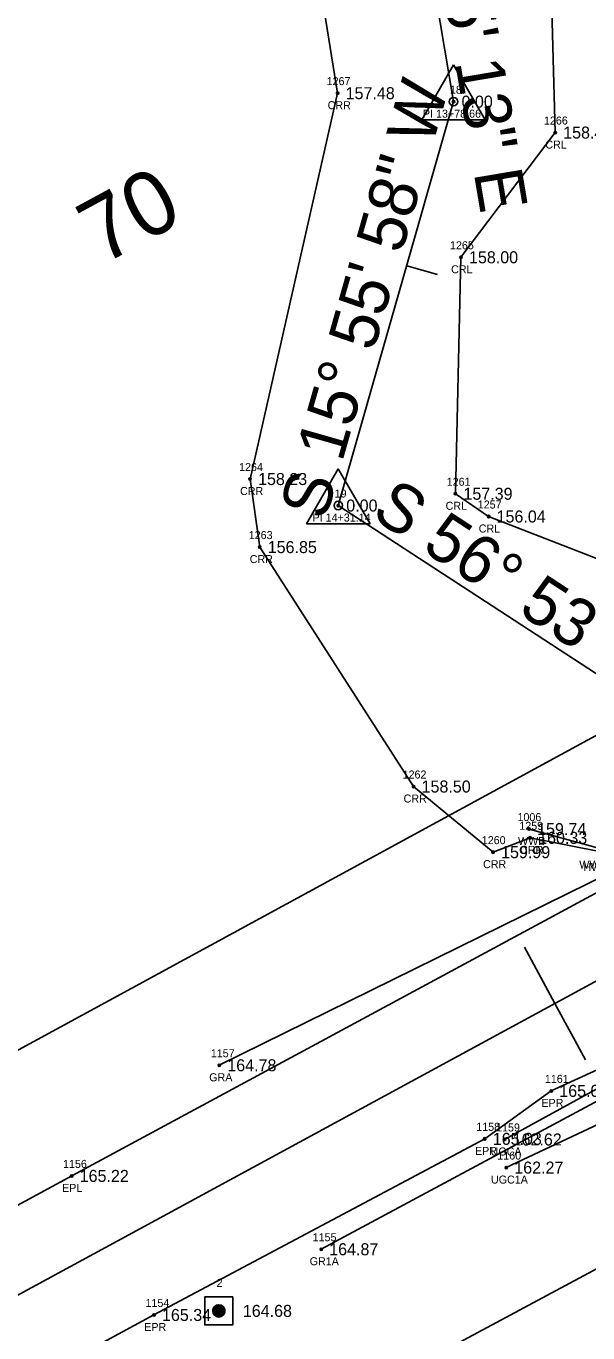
# Model space of a CAD drawing. Extents: x 2279339 to 2281902, y 1061267 to 1062892.
# Drawn here: x 2280137.2 to 2280207.4, y 1061741.1 to 1061904.3 of the extents above; entities that cross this region are included whole.
import ezdxf

# ---------------------------------------------------------------- set-up
doc = ezdxf.new("R2010")
doc.units = 0
for name, color, linetype in [('RD_EX_Bridge', 7, 'Continuous'), ('RD_EX_Bridge_txCode', 7, 'Continuous'), ('RD_EX_GuardRail', 7, 'Continuous'), ('RD_EX_GuardRail_txCode', 7, 'Continuous'), ('RD_EX_H2O', 7, 'Continuous'), ('RD_EX_H2O_txCode', 7, 'Continuous'), ('RD_EX_Road', 7, 'Continuous'), ('RD_EX_Road_txCode', 7, 'Continuous'), ('RD_EX_TX_Bridge_ELEV', 7, 'Continuous'), ('RD_EX_TX_GuardRail_ELEV', 7, 'Continuous'), ('RD_EX_TX_H2O_ELEV', 7, 'Continuous'), ('RD_EX_TX_Road_ELEV', 7, 'Continuous'), ('RD_EX_TX_UT_ELEV', 7, 'Continuous'), ('RD_EX_UT', 7, 'Continuous'), ('RD_EX_UT_txCode', 7, 'Continuous'), ('RD_EX_VEG', 7, 'Continuous'), ('RD_HC_Cl', 7, 'Continuous'), ('RD_HC_Data', 7, 'Continuous'), ('RD_HC_Data_Tic', 7, 'Continuous'), ('RD_HC_Survey', 7, 'Continuous'), ('RD_HC_Survey_ELEV', 7, 'Continuous'), ('RD_HC_Survey_txCode', 7, 'Continuous'), ('RD_HC_TX_Sta50', 7, 'Continuous'), ('RD_HC_txCode', 7, 'Continuous'), ('RD_SMD_Locator', 7, 'Continuous')]:
    doc.layers.add(name, color=color, linetype=linetype)

msp = doc.modelspace()

# ---------------------------------------------------------------- linework, layer by layer
at = {"layer": 'RD_EX_Bridge'}
msp.add_line((2280210.72, 1061801.1), (2280200.05, 1061804.04), dxfattribs=at)
at = {"layer": 'RD_EX_GuardRail'}
msp.add_line((2280174.08, 1061751.56), (2280309.28, 1061824.13), dxfattribs=at)
msp.add_lwpolyline([(2280161.35, 1061774.54), (2280212.91, 1061799.96), (2280228.59, 1061807.39), (2280248.74, 1061818.9), (2280296.23, 1061848.19)], dxfattribs=at)
at = {"layer": 'RD_EX_H2O'}
for points in [[(2280211.16, 1061800.79), (2280200.18, 1061802.95), (2280195.55, 1061801.16), (2280185.62, 1061809.36), (2280166.4, 1061839.27), (2280165.19, 1061847.77), (2280176.13, 1061895.97), (2280173.38, 1061913.11), (2280146.96, 1061940.88), (2280090.97, 1061964.76), (2280049.27, 1062002.4), (2280058.65, 1062048.88), (2280050.78, 1062064.28), (2280035.9, 1062083.09), (2280001.73, 1062095.49), (2279975.65, 1062129.45), (2279976.82, 1062173.44)], [(2280247.67, 1061820.22), (2280254.15, 1061833.04), (2280250.13, 1061833.61), (2280244.17, 1061836.72), (2280240.97, 1061826.97), (2280234.88, 1061827.59), (2280194.99, 1061843.09), (2280190.85, 1061845.93), (2280191.54, 1061875.47), (2280203.31, 1061891.05), (2280202.74, 1061912.57), (2280161.92, 1061962.77), (2280106.66, 1061987.64), (2280081.48, 1062000.69), (2280077.59, 1062019.21), (2280091.23, 1062055.4), (2280068.77, 1062094.03), (2280025.87, 1062122.57), (2280008.58, 1062126.75), (2280003.39, 1062153.96)]]:
    msp.add_lwpolyline(points, dxfattribs=at)
at = {"layer": 'RD_EX_Road'}
for points in [[(2279554.31, 1061441.46), (2279636.61, 1061486.51), (2279673.46, 1061506.76), (2279683.06, 1061512.21), (2279723.14, 1061533.54), (2279809.28, 1061580.29), (2279896.91, 1061627.91), (2279977.07, 1061671.02), (2280059.64, 1061715.57), (2280142.91, 1061760.72), (2280228.83, 1061807.06), (2280306.04, 1061849.18), (2280392.98, 1061896.71), (2280482.82, 1061945.75), (2280567.83, 1061991.78), (2280649.94, 1062036.55), (2280660.56, 1062042.19), (2280676.12, 1062050.66), (2280737.28, 1062083.64), (2280828.54, 1062132.77), (2280887.86, 1062164.61), (2280934.91, 1062190.9)], [(2279906, 1061609.76), (2279987.33, 1061653.65), (2280069.09, 1061697.76), (2280153.19, 1061743.35), (2280194.51, 1061765.35), (2280202.82, 1061771.34), (2280211.47, 1061775.32), (2280215.93, 1061780.7), (2280225.22, 1061785.77), (2280231.78, 1061787.38), (2280251.88, 1061797.82), (2280255.66, 1061801.36), (2280256.83, 1061804.75), (2280266.2, 1061806.83), (2280270.78, 1061807.29), (2280284.33, 1061814.31), (2280315.09, 1061831.32), (2280403.05, 1061879.04)]]:
    msp.add_lwpolyline(points, dxfattribs=at)
at = {"layer": 'RD_EX_UT'}
for points in [[(2280196.99, 1061765.27), (2280221.15, 1061778.49), (2280271.76, 1061806.05)], [(2280197.2, 1061761.76), (2280217.04, 1061771.11), (2280221.15, 1061778.49)]]:
    msp.add_lwpolyline(points, dxfattribs=at)
at = {"layer": 'RD_EX_VEG'}
for points in [[(2279558.89, 1061483.89), (2279567.79, 1061465.98), (2279895.37, 1061645.37), (2280383.77, 1061911.19), (2280927.05, 1062203.11)], [(2279742.03, 1061456.73), (2279738.34, 1061498.5), (2279914.03, 1061591.25), (2280293.74, 1061794.82), (2280950.97, 1062158.54)]]:
    msp.add_lwpolyline(points, dxfattribs=at)
at = {"layer": 'RD_HC_Cl'}
for p, q in [((2279559.77, 1061433.17), (2280939.55, 1062181.67)), ((2280187.29, 1061914.59), (2280190.61, 1061894.91)), ((2280190.61, 1061894.91), (2280176.21, 1061844.46)), ((2280176.21, 1061844.46), (2280228.65, 1061810.26))]:
    msp.add_line(p, q, dxfattribs=at)
at = {"layer": 'RD_HC_Data'}
for p, q in [((2280186.64, 1061892.62), (2280190.61, 1061899.5)), ((2280190.61, 1061899.5), (2280194.58, 1061892.62)), ((2280186.64, 1061892.62), (2280194.58, 1061892.62)), ((2280172.24, 1061842.16), (2280176.21, 1061849.04)), ((2280176.21, 1061849.04), (2280180.18, 1061842.16)), ((2280172.24, 1061842.16), (2280180.18, 1061842.16))]:
    msp.add_line(p, q, dxfattribs=at)
for centre in [(2280190.61, 1061894.91), (2280176.21, 1061844.46)]:
    msp.add_circle(centre, 0.529, dxfattribs=at)
at = {"layer": 'RD_HC_Data_Tic'}
for p, q in [((2280184.76, 1061874.39), (2280188.6, 1061873.3)), ((2280203.28, 1061782.26), (2280199.46, 1061789.29)), ((2280203.28, 1061782.26), (2280207.09, 1061775.22))]:
    msp.add_line(p, q, dxfattribs=at)
at = {"layer": 'RD_HC_Survey'}
for p, q in [((2280160.54, 1061743.69), (2280160.54, 1061744.04)), ((2280160.57, 1061743.6), (2280160.57, 1061744.13)), ((2280160.59, 1061743.54), (2280160.59, 1061744.19)), ((2280160.62, 1061743.49), (2280160.62, 1061744.24)), ((2280160.64, 1061743.45), (2280160.64, 1061744.28)), ((2280160.67, 1061743.41), (2280160.67, 1061744.31)), ((2280160.69, 1061743.38), (2280160.69, 1061744.35)), ((2280160.72, 1061743.35), (2280160.72, 1061744.38)), ((2280160.74, 1061743.33), (2280160.74, 1061744.4)), ((2280160.77, 1061743.3), (2280160.77, 1061744.43)), ((2280160.79, 1061743.28), (2280160.79, 1061744.45)), ((2280160.82, 1061743.26), (2280160.82, 1061744.47)), ((2280160.84, 1061743.24), (2280160.84, 1061744.49)), ((2280160.86, 1061743.22), (2280160.86, 1061744.5)), ((2280160.89, 1061743.21), (2280160.89, 1061744.52)), ((2280160.91, 1061743.19), (2280160.91, 1061744.54)), ((2280160.94, 1061743.18), (2280160.94, 1061744.55)), ((2280160.96, 1061743.17), (2280160.96, 1061744.56)), ((2280160.99, 1061743.16), (2280160.99, 1061744.57)), ((2280161.01, 1061743.15), (2280161.01, 1061744.58)), ((2280161.04, 1061743.14), (2280161.04, 1061744.59)), ((2280161.06, 1061743.13), (2280161.06, 1061744.6)), ((2280161.09, 1061743.12), (2280161.09, 1061744.61)), ((2280161.11, 1061743.12), (2280161.11, 1061744.61)), ((2280161.14, 1061743.11), (2280161.14, 1061744.62)), ((2280161.16, 1061743.11), (2280161.16, 1061744.62)), ((2280161.19, 1061743.1), (2280161.19, 1061744.63)), ((2280161.21, 1061743.1), (2280161.21, 1061744.63)), ((2280161.24, 1061743.1), (2280161.24, 1061744.63)), ((2280161.26, 1061743.1), (2280161.26, 1061744.63)), ((2280161.29, 1061743.09), (2280161.29, 1061744.63)), ((2280161.31, 1061743.1), (2280161.31, 1061744.63)), ((2280161.34, 1061743.1), (2280161.34, 1061744.63)), ((2280161.36, 1061743.1), (2280161.36, 1061744.63)), ((2280161.38, 1061743.1), (2280161.38, 1061744.63)), ((2280161.41, 1061743.1), (2280161.41, 1061744.62)), ((2280161.43, 1061743.11), (2280161.43, 1061744.62)), ((2280161.46, 1061743.11), (2280161.46, 1061744.62)), ((2280161.48, 1061743.12), (2280161.48, 1061744.61)), ((2280161.51, 1061743.13), (2280161.51, 1061744.6)), ((2280161.53, 1061743.13), (2280161.53, 1061744.59)), ((2280161.56, 1061743.14), (2280161.56, 1061744.59)), ((2280161.58, 1061743.15), (2280161.58, 1061744.58)), ((2280161.61, 1061743.16), (2280161.61, 1061744.57)), ((2280161.63, 1061743.17), (2280161.63, 1061744.55)), ((2280161.66, 1061743.19), (2280161.66, 1061744.54)), ((2280161.68, 1061743.2), (2280161.68, 1061744.53)), ((2280161.71, 1061743.22), (2280161.71, 1061744.51)), ((2280161.73, 1061743.23), (2280161.73, 1061744.5)), ((2280161.76, 1061743.25), (2280161.76, 1061744.48)), ((2280161.78, 1061743.27), (2280161.78, 1061744.46)), ((2280161.81, 1061743.29), (2280161.81, 1061744.44)), ((2280161.83, 1061743.31), (2280161.83, 1061744.41)), ((2280161.85, 1061743.34), (2280161.85, 1061744.39)), ((2280161.88, 1061743.37), (2280161.88, 1061744.36)), ((2280161.9, 1061743.4), (2280161.9, 1061744.33)), ((2280161.93, 1061743.43), (2280161.93, 1061744.3)), ((2280161.95, 1061743.47), (2280161.95, 1061744.26)), ((2280161.98, 1061743.52), (2280161.98, 1061744.21)), ((2280162, 1061743.57), (2280162, 1061744.16)), ((2280162.03, 1061743.64), (2280162.03, 1061744.09)), ((2280162.05, 1061743.75), (2280162.05, 1061743.98))]:
    msp.add_line(p, q, dxfattribs=at)
msp.add_lwpolyline([(2280163.04, 1061745.61), (2280159.54, 1061745.61), (2280159.54, 1061742.11), (2280163.04, 1061742.11)], close=True, dxfattribs=at)
msp.add_circle((2280161.29, 1061743.86), 0.769, dxfattribs=at)
at = {"layer": 'RD_SMD_Locator'}
for centre in [(2280176.13, 1061895.97), (2280190.61, 1061894.91), (2280203.31, 1061891.05), (2280191.54, 1061875.47), (2280165.19, 1061847.77), (2280190.85, 1061845.93), (2280176.21, 1061844.46), (2280194.99, 1061843.09), (2280166.4, 1061839.27), (2280185.62, 1061809.36), (2280200.05, 1061804.04), (2280200.18, 1061802.95), (2280195.55, 1061801.16), (2280161.35, 1061774.54), (2280202.82, 1061771.34), (2280194.51, 1061765.35), (2280196.99, 1061765.27), (2280197.2, 1061761.76), (2280142.91, 1061760.72), (2280174.08, 1061751.56), (2280161.29, 1061743.86), (2280153.19, 1061743.35)]:
    msp.add_circle(centre, 0.15, dxfattribs=at)

# ---------------------------------------------------------------- texts
at = {"layer": 'RD_EX_Bridge_txCode'}
for s, p in [('1006', (2280198.6, 1061805.04)), ('WWB', (2280198.67, 1061802.04)), ('WWA 16ROCK', (2280206.32, 1061799.1)), ('HWA 16ROCK', (2280206.85, 1061798.79))]:
    msp.add_text(s, height=1, dxfattribs=at).set_placement(p)
at = {"layer": 'RD_EX_GuardRail_txCode'}
for s, p in [('1157', (2280160.29, 1061775.54)), ('GRA', (2280160.09, 1061772.54)), ('1155', (2280173.01, 1061752.56)), ('GR1A', (2280172.64, 1061749.56))]:
    msp.add_text(s, height=1, dxfattribs=at).set_placement(p)
at = {"layer": 'RD_EX_H2O_txCode'}
for s, p in [('1267', (2280174.76, 1061896.97)), ('CRR', (2280174.88, 1061893.97)), ('1266', (2280201.91, 1061892.05)), ('CRL', (2280202.08, 1061889.05)), ('1265', (2280190.17, 1061876.47)), ('CRL', (2280190.31, 1061873.47)), ('1264', (2280163.82, 1061848.77)), ('CRR', (2280163.94, 1061845.77)), ('1261', (2280189.76, 1061846.93)), ('CRL', (2280189.62, 1061843.93)), ('1257', (2280193.64, 1061844.09)), ('CRL', (2280193.76, 1061841.09)), ('1263', (2280165.03, 1061840.27)), ('CRR', (2280165.15, 1061837.27)), ('1262', (2280184.25, 1061810.36)), ('CRR', (2280184.37, 1061807.36)), ('1259', (2280198.83, 1061803.95)), ('1260', (2280194.14, 1061802.16)), ('CRR', (2280198.93, 1061800.95)), ('CRR', (2280194.3, 1061799.16))]:
    msp.add_text(s, height=1, dxfattribs=at).set_placement(p)
at = {"layer": 'RD_EX_Road_txCode'}
for s, p in [('1161', (2280202.02, 1061772.34)), ('EPR', (2280201.59, 1061769.34)), ('1158', (2280193.45, 1061766.35)), ('EPR', (2280193.29, 1061763.35)), ('1156', (2280141.83, 1061761.72)), ('EPL', (2280141.71, 1061758.72)), ('1154', (2280152.13, 1061744.35)), ('EPR', (2280151.97, 1061741.35))]:
    msp.add_text(s, height=1, dxfattribs=at).set_placement(p)
at = {"layer": 'RD_EX_TX_Bridge_ELEV'}
msp.add_text('159.74', height=1.5, dxfattribs=at).set_placement((2280201.05, 1061803.29))
at = {"layer": 'RD_EX_TX_GuardRail_ELEV'}
for s, p in [('164.78', (2280162.35, 1061773.79)), ('164.87', (2280175.08, 1061750.81))]:
    msp.add_text(s, height=1.5, dxfattribs=at).set_placement(p)
at = {"layer": 'RD_EX_TX_H2O_ELEV'}
for s, p in [('157.48', (2280177.13, 1061895.22)), ('158.43', (2280204.31, 1061890.3)), ('158.00', (2280192.54, 1061874.72)), ('158.23', (2280166.19, 1061847.02)), ('157.39', (2280191.85, 1061845.18)), ('156.04', (2280195.99, 1061842.34)), ('156.85', (2280167.4, 1061838.52)), ('158.50', (2280186.62, 1061808.61)), ('160.33', (2280201.18, 1061802.2)), ('159.99', (2280196.55, 1061800.41))]:
    msp.add_text(s, height=1.5, dxfattribs=at).set_placement(p)
at = {"layer": 'RD_EX_TX_Road_ELEV'}
for s, p in [('165.06', (2280203.82, 1061770.59)), ('165.03', (2280195.51, 1061764.6)), ('165.22', (2280143.91, 1061759.97)), ('165.34', (2280154.19, 1061742.6))]:
    msp.add_text(s, height=1.5, dxfattribs=at).set_placement(p)
at = {"layer": 'RD_EX_TX_UT_ELEV'}
for s, p in [('162.62', (2280197.99, 1061764.52)), ('162.27', (2280198.2, 1061761.01))]:
    msp.add_text(s, height=1.5, dxfattribs=at).set_placement(p)
at = {"layer": 'RD_EX_UT_txCode'}
for s, p in [('1159', (2280195.93, 1061766.27)), ('UGCA', (2280195.24, 1061763.27)), ('1160', (2280196.08, 1061762.76)), ('UGC1A', (2280195.29, 1061759.76))]:
    msp.add_text(s, height=1, dxfattribs=at).set_placement(p)
at = {"layer": 'RD_HC_Data'}
for s, rotation, p in [('S 9%%d 35\' 13" E', 279.587, (2280185.77, 1061929.61)), ('S 15%%d 55\' 58" W', 74.0672, (2280174.6, 1061842.47)), ('S 56%%d 53\' 35" E', 326.893, (2280180.15, 1061843.08))]:
    msp.add_text(s, height=6, rotation=rotation, dxfattribs=at).set_placement(p)
at = {"layer": 'RD_HC_Survey_ELEV'}
for s, p in [('0.00', (2280191.61, 1061894.16)), ('0.00', (2280177.21, 1061843.71)), ('164.68', (2280164.29, 1061743.11))]:
    msp.add_text(s, height=1.5, dxfattribs=at).set_placement(p)
at = {"layer": 'RD_HC_Survey_txCode'}
msp.add_text('2', height=1, dxfattribs=at).set_placement((2280161.01, 1061746.86))
at = {"layer": 'RD_HC_TX_Sta50'}
msp.add_text('70', height=8, rotation=28.4787, dxfattribs=at).set_placement((2280146.69, 1061874.42))
at = {"layer": 'RD_HC_txCode'}
for s, p in [('18', (2280190.16, 1061895.91)), ('PI 13+78.66', (2280186.79, 1061892.91)), ('19', (2280175.76, 1061845.46)), ('PI 14+31.14', (2280173, 1061842.46))]:
    msp.add_text(s, height=1, dxfattribs=at).set_placement(p)

doc.saveas('drawing.dxf')
